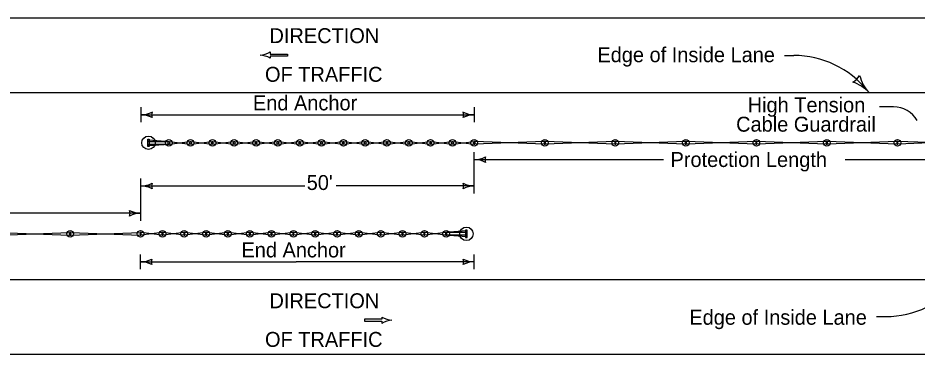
# Model space of a CAD drawing. Extents: x 10133 to 81668, y 7924 to 11018.
# Drawn here: x 10688 to 11411, y 8927 to 9197 of the extents above; entities that cross this region are included whole.
import ezdxf

# ---------------------------------------------------------------- set-up
doc = ezdxf.new("R2010")
doc.units = 0
for name, color, linetype in [('dsnCellElements', 7, 'Continuous'), ('DsnShtRevisedText', 7, 'Continuous'), ('dsnStdDimension', 7, 'Continuous')]:
    doc.layers.add(name, color=color, linetype=linetype)

msp = doc.modelspace()

# ---------------------------------------------------------------- linework, layer by layer
at = {"layer": 'dsnCellElements'}
for p, q in [((10793.26, 9099.32), (10810.02, 9098.13)), ((10793.26, 9098.13), (10809.09, 9098.13)), ((10793.26, 9095.88), (10809.09, 9095.88)), ((10793.26, 9094.7), (10810.02, 9095.88)), ((10810.02, 9095.88), (10826.6, 9098.14)), ((10810.02, 9098.13), (10826.6, 9095.89)), ((10827.54, 9098.14), (10844.17, 9095.88)), ((10827.54, 9095.89), (10844.17, 9098.13)), ((10845.12, 9095.88), (10861.7, 9098.14)), ((10845.12, 9098.13), (10861.7, 9095.89)), ((10862.64, 9098.14), (10879.27, 9095.88)), ((10862.64, 9095.89), (10879.27, 9098.13)), ((10880.22, 9095.88), (10896.8, 9098.14)), ((10880.22, 9098.13), (10896.8, 9095.89)), ((10897.74, 9098.14), (10914.37, 9095.88)), ((10897.74, 9095.89), (10914.37, 9098.13)), ((10915.31, 9095.88), (10931.89, 9098.14)), ((10915.31, 9098.13), (10931.89, 9095.89)), ((10932.83, 9098.14), (10949.46, 9095.88)), ((10932.83, 9095.89), (10949.46, 9098.14)), ((10950.4, 9098.14), (10966.98, 9095.89)), ((10950.4, 9095.88), (10966.98, 9098.14)), ((10967.92, 9098.14), (10984.55, 9095.89)), ((10967.92, 9095.89), (10984.55, 9098.14)), ((10985.49, 9098.14), (11002.07, 9095.89)), ((10985.49, 9095.89), (11002.07, 9098.14)), ((11003.01, 9098.14), (11019.64, 9095.89)), ((11003.01, 9095.89), (11019.64, 9098.14)), ((11020.58, 9098.14), (11037.16, 9095.89)), ((11020.58, 9095.89), (11037.16, 9098.14)), ((11038.1, 9098.14), (11054.73, 9095.89)), ((11038.1, 9095.89), (11054.73, 9098.14)), ((11111.43, 9098.14), (11055.67, 9095.89)), ((11111.43, 9095.89), (11055.67, 9098.14)), ((11168.14, 9098.14), (11112.37, 9095.89)), ((11168.14, 9095.89), (11112.37, 9098.14)), ((11224.84, 9098.14), (11169.08, 9095.89)), ((11224.84, 9095.89), (11169.08, 9098.14)), ((11281.54, 9098.14), (11225.78, 9095.89)), ((11281.54, 9095.89), (11225.78, 9098.14)), ((11338.24, 9098.14), (11282.48, 9095.89)), ((11338.24, 9095.89), (11282.48, 9098.14)), ((11394.94, 9098.14), (11339.18, 9095.89)), ((11394.94, 9095.89), (11339.18, 9098.14)), ((11451.64, 9098.14), (11395.88, 9095.89)), ((11451.64, 9095.89), (11395.88, 9098.14)), ((10674, 9022.69), (10729.76, 9024.94)), ((10674, 9024.94), (10729.76, 9022.69)), ((10730.7, 9022.69), (10786.46, 9024.94)), ((10730.7, 9024.94), (10786.46, 9022.69)), ((10804.03, 9024.94), (10787.4, 9022.69)), ((10804.03, 9022.69), (10787.4, 9024.94)), ((10821.55, 9024.94), (10804.97, 9022.69)), ((10821.55, 9022.69), (10804.97, 9024.94)), ((10839.12, 9024.94), (10822.49, 9022.69)), ((10839.12, 9022.69), (10822.49, 9024.94)), ((10856.64, 9024.94), (10840.06, 9022.69)), ((10856.64, 9022.69), (10840.06, 9024.94)), ((10874.21, 9024.94), (10857.58, 9022.69)), ((10874.21, 9022.69), (10857.58, 9024.94)), ((10891.73, 9024.94), (10875.15, 9022.69)), ((10891.73, 9022.69), (10875.15, 9024.94)), ((10909.3, 9024.94), (10892.67, 9022.69)), ((10909.3, 9022.69), (10892.67, 9024.94)), ((10926.82, 9022.69), (10910.24, 9024.94)), ((10926.82, 9024.94), (10910.24, 9022.69)), ((10944.39, 9024.94), (10927.76, 9022.69)), ((10944.39, 9022.69), (10927.76, 9024.94)), ((10961.91, 9024.94), (10945.33, 9022.69)), ((10961.91, 9022.69), (10945.33, 9024.94)), ((10979.49, 9024.94), (10962.86, 9022.69)), ((10979.49, 9022.69), (10962.86, 9024.94)), ((10997.02, 9024.94), (10980.43, 9022.69)), ((10997.02, 9022.69), (10980.43, 9024.94)), ((11014.6, 9024.94), (10997.96, 9022.69)), ((11014.6, 9022.69), (10997.96, 9024.94)), ((11032.12, 9024.94), (11015.53, 9022.69)), ((11032.12, 9022.69), (11015.53, 9024.94)), ((11048.88, 9026.12), (11032.12, 9024.94)), ((11048.88, 9021.51), (11032.12, 9022.69)), ((11048.88, 9024.94), (11033.05, 9024.94)), ((11048.88, 9022.69), (11033.05, 9022.69))]:
    msp.add_line(p, q, dxfattribs=at)
for points in [[(10792.65, 9094.01), (10792.65, 9100.02), (10793.87, 9100.02), (10793.87, 9094.01)], [(10809.08, 9095.88), (10809.08, 9098.13), (10810.02, 9098.13), (10810.02, 9095.88)], [(10826.6, 9095.89), (10826.6, 9098.14), (10827.54, 9098.14), (10827.54, 9095.89)], [(10844.18, 9095.88), (10844.18, 9098.13), (10845.12, 9098.13), (10845.12, 9095.88)], [(10861.7, 9095.89), (10861.7, 9098.14), (10862.64, 9098.14), (10862.64, 9095.89)], [(10879.28, 9095.88), (10879.28, 9098.13), (10880.22, 9098.13), (10880.22, 9095.88)], [(10896.8, 9095.89), (10896.8, 9098.14), (10897.74, 9098.14), (10897.74, 9095.89)], [(10914.37, 9095.88), (10914.37, 9098.13), (10915.31, 9098.13), (10915.31, 9095.88)], [(10931.89, 9095.89), (10931.89, 9098.14), (10932.83, 9098.14), (10932.83, 9095.89)], [(10949.46, 9095.88), (10949.46, 9098.14), (10950.4, 9098.14), (10950.4, 9095.88)], [(10966.98, 9095.89), (10966.98, 9098.14), (10967.92, 9098.14), (10967.92, 9095.89)], [(10984.55, 9095.89), (10984.55, 9098.14), (10985.49, 9098.14), (10985.49, 9095.89)], [(11002.07, 9095.89), (11002.07, 9098.14), (11003.01, 9098.14), (11003.01, 9095.89)], [(11019.64, 9095.89), (11019.64, 9098.14), (11020.58, 9098.14), (11020.58, 9095.89)], [(11037.16, 9095.89), (11037.16, 9098.14), (11038.1, 9098.14), (11038.1, 9095.89)], [(11055.67, 9095.89), (11055.67, 9098.14), (11054.73, 9098.14), (11054.73, 9095.89)], [(11054.73, 9095.89), (11054.73, 9098.14), (11055.67, 9098.14), (11055.67, 9095.89)], [(11112.37, 9095.89), (11112.37, 9098.14), (11111.43, 9098.14), (11111.43, 9095.89)], [(11112.37, 9095.89), (11112.37, 9098.14), (11111.43, 9098.14), (11111.43, 9095.89)], [(11169.08, 9095.89), (11169.08, 9098.14), (11168.14, 9098.14), (11168.14, 9095.89)], [(11169.08, 9095.89), (11169.08, 9098.14), (11168.14, 9098.14), (11168.14, 9095.89)], [(11225.78, 9095.89), (11225.78, 9098.14), (11224.84, 9098.14), (11224.84, 9095.89)], [(11225.78, 9095.89), (11225.78, 9098.14), (11224.84, 9098.14), (11224.84, 9095.89)], [(11282.48, 9095.89), (11282.48, 9098.14), (11281.54, 9098.14), (11281.54, 9095.89)], [(11282.48, 9095.89), (11282.48, 9098.14), (11281.54, 9098.14), (11281.54, 9095.89)], [(11339.18, 9095.89), (11339.18, 9098.14), (11338.24, 9098.14), (11338.24, 9095.89)], [(11339.18, 9095.89), (11339.18, 9098.14), (11338.24, 9098.14), (11338.24, 9095.89)], [(11395.88, 9095.89), (11395.88, 9098.14), (11394.94, 9098.14), (11394.94, 9095.89)], [(11395.88, 9095.89), (11395.88, 9098.14), (11394.94, 9098.14), (11394.94, 9095.89)], [(10729.76, 9024.94), (10729.76, 9022.69), (10730.7, 9022.69), (10730.7, 9024.94)], [(10729.76, 9024.94), (10729.76, 9022.69), (10730.7, 9022.69), (10730.7, 9024.94)], [(10786.46, 9024.94), (10786.46, 9022.69), (10787.4, 9022.69), (10787.4, 9024.94)], [(10787.4, 9022.69), (10787.4, 9024.94), (10786.46, 9024.94), (10786.46, 9022.69)], [(10804.97, 9022.69), (10804.97, 9024.94), (10804.03, 9024.94), (10804.03, 9022.69)], [(10822.49, 9022.69), (10822.49, 9024.94), (10821.55, 9024.94), (10821.55, 9022.69)], [(10840.06, 9022.69), (10840.06, 9024.94), (10839.12, 9024.94), (10839.12, 9022.69)], [(10857.58, 9022.69), (10857.58, 9024.94), (10856.64, 9024.94), (10856.64, 9022.69)], [(10875.15, 9022.69), (10875.15, 9024.94), (10874.21, 9024.94), (10874.21, 9022.69)], [(10892.67, 9022.69), (10892.67, 9024.94), (10891.73, 9024.94), (10891.73, 9022.69)], [(10910.24, 9022.69), (10910.24, 9024.94), (10909.3, 9024.94), (10909.3, 9022.69)], [(10927.76, 9022.69), (10927.76, 9024.94), (10926.82, 9024.94), (10926.82, 9022.69)], [(10945.33, 9022.69), (10945.33, 9024.94), (10944.39, 9024.94), (10944.39, 9022.69)], [(10962.85, 9022.69), (10962.85, 9024.94), (10961.91, 9024.94), (10961.91, 9022.69)], [(10980.43, 9022.69), (10980.43, 9024.94), (10979.49, 9024.94), (10979.49, 9022.69)], [(10997.95, 9022.69), (10997.95, 9024.94), (10997.02, 9024.94), (10997.02, 9022.69)], [(11015.53, 9022.69), (11015.53, 9024.94), (11014.6, 9024.94), (11014.6, 9022.69)], [(11033.05, 9022.69), (11033.05, 9024.94), (11032.12, 9024.94), (11032.12, 9022.69)], [(11049.48, 9020.81), (11049.48, 9026.82), (11048.27, 9026.82), (11048.27, 9020.81)]]:
    msp.add_lwpolyline(points, close=True, dxfattribs=at)
for centre, radius in [((10793.26, 9097.01), 5.4), ((10809.55, 9097.01), 2.66), ((10827.07, 9097.01), 2.66), ((10844.65, 9097.01), 2.66), ((10862.17, 9097.01), 2.66), ((10879.75, 9097.01), 2.66), ((10897.27, 9097.01), 2.66), ((10914.84, 9097.01), 2.66), ((10932.36, 9097.01), 2.66), ((10949.93, 9097.01), 2.66), ((10967.45, 9097.01), 2.66), ((10985.02, 9097.01), 2.66), ((11002.54, 9097.01), 2.66), ((11020.11, 9097.01), 2.66), ((11037.63, 9097.01), 2.66), ((11055.2, 9097.01), 2.66), ((11055.2, 9097.01), 2.66), ((11111.9, 9097.01), 2.66), ((11111.9, 9097.01), 2.66), ((11168.61, 9097.01), 2.66), ((11168.61, 9097.01), 2.66), ((11225.31, 9097.01), 2.66), ((11225.31, 9097.01), 2.66), ((11282.01, 9097.01), 2.66), ((11282.01, 9097.01), 2.66), ((11338.71, 9097.01), 2.66), ((11338.71, 9097.01), 2.66), ((11395.41, 9097.01), 2.66), ((11395.41, 9097.01), 2.66), ((11048.88, 9023.82), 5.4), ((10730.23, 9023.82), 2.66), ((10730.23, 9023.82), 2.66), ((10786.93, 9023.82), 2.66), ((10786.93, 9023.82), 2.66), ((10804.5, 9023.82), 2.66), ((10822.02, 9023.82), 2.66), ((10839.59, 9023.82), 2.66), ((10857.11, 9023.82), 2.66), ((10874.68, 9023.82), 2.66), ((10892.2, 9023.82), 2.66), ((10909.77, 9023.82), 2.66), ((10927.29, 9023.82), 2.66), ((10944.86, 9023.82), 2.66), ((10962.38, 9023.82), 2.66), ((10979.96, 9023.82), 2.66), ((10997.48, 9023.82), 2.66), ((11015.06, 9023.82), 2.66), ((11032.59, 9023.82), 2.66)]:
    msp.add_circle(centre, radius, dxfattribs=at)
at = {"layer": 'DsnShtRevisedText'}
for p, q in [((10882.95, 9167.45), (10882.95, 9167.45)), ((10891.05, 9169.99), (10891.05, 9168.21)), ((10891.05, 9168.21), (10905.02, 9168.21)), ((10905.02, 9166.69), (10891.05, 9166.69)), ((10891.05, 9166.69), (10891.05, 9164.91)), ((10905.02, 9168.21), (10905.02, 9166.69)), ((11304.72, 9167.13), (11312.16, 9167.13)), ((10787.1, 9125.49), (10787.1, 9113.49)), ((11055.2, 9125.49), (11055.2, 9113.49)), ((11392.4, 9125.82), (11381.15, 9125.82)), ((10787.1, 9119.49), (11055.2, 9119.49)), ((11055.2, 9056.27), (11055.2, 9089.49)), ((11055.2, 9083.49), (11207.39, 9083.49)), ((11353.36, 9083.49), (11471.89, 9083.49)), ((10787.1, 9034.37), (10787.1, 9068.27)), ((10787.1, 9062.27), (10919.01, 9062.27)), ((11055.2, 9062.27), (10944.03, 9062.27)), ((10787.1, 9040.37), (10572.76, 9040.37)), ((10786.93, 8995.34), (10786.93, 9007.34)), ((11055.2, 8995.34), (11055.2, 9007.34)), ((10786.93, 9001.34), (10911.91, 9001.34)), ((11055.2, 9001.34), (10911.91, 9001.34)), ((10980.89, 8956.98), (10980.89, 8955.2)), ((11378.63, 8957.41), (11386.08, 8957.41)), ((10980.89, 8955.2), (10966.93, 8955.2)), ((10966.93, 8955.2), (10966.93, 8953.68)), ((10966.93, 8953.68), (10980.89, 8953.68)), ((10980.89, 8953.68), (10980.89, 8951.9)), ((10988.99, 8954.44), (10988.99, 8954.44))]:
    msp.add_line(p, q, dxfattribs=at)
for centre, radius, start, end in [((10882.28, 9183.81), 16.37, 272.35199, 302.38203), ((10882.28, 9151.09), 16.37, 57.61797, 87.64801), ((11312.16, 9090.94), 76.18, 39.01063, 90), ((11354.17, 9157.13), 12.51, 295.26394, 330.73064), ((11349, 9115.19), 32.38, 42.99729, 71.06977), ((11396.36, 9159.35), 32.38, 194.9248, 222.99729), ((11392.4, 9104.06), 21.76, 30.22434, 90), ((10787.1, 9138.61), 19.13, 270, 298.07249), ((10787.1, 9100.36), 19.13, 61.92751, 90), ((10803.13, 9119.49), 7.39, 162.26665, 197.73335), ((11039.17, 9119.49), 7.39, 342.26665, 17.73335), ((11055.2, 9138.61), 19.13, 241.92751, 270), ((11055.2, 9100.36), 19.13, 90, 118.07249), ((11055.2, 9102.61), 19.13, 270, 298.07249), ((11055.2, 9064.36), 19.13, 61.92751, 90), ((11071.24, 9083.49), 7.39, 162.26665, 197.73335), ((10787.1, 9081.39), 19.13, 270, 298.07249), ((10787.1, 9043.14), 19.13, 61.92751, 90), ((10803.13, 9062.27), 7.39, 162.26665, 197.73335), ((11039.17, 9062.27), 7.39, 342.26665, 17.73335), ((11055.2, 9081.39), 19.13, 241.92751, 270), ((11055.2, 9043.14), 19.13, 90, 118.07249), ((10771.06, 9040.37), 7.39, 342.26665, 17.73335), ((10787.1, 9059.5), 19.13, 241.92751, 270), ((10787.1, 9021.25), 19.13, 90, 118.07249), ((10786.93, 9020.47), 19.13, 270, 298.07249), ((10786.93, 8982.22), 19.13, 61.92751, 90), ((10802.97, 9001.34), 7.39, 162.26665, 197.73335), ((11039.17, 9001.34), 7.39, 342.26665, 17.73335), ((11055.2, 9020.47), 19.13, 241.92751, 270), ((11055.2, 8982.22), 19.13, 90, 118.07249), ((11386.08, 9033.59), 76.18, 270, 320.98937), ((10989.66, 8970.8), 16.37, 237.61797, 267.64801), ((10989.66, 8938.08), 16.37, 92.35199, 122.38203)]:
    msp.add_arc(centre, radius, start, end, dxfattribs=at)
at = {"layer": 'dsnStdDimension'}
for p, q in [((10362.19, 9197.27), (11477.85, 9197.27)), ((10362.19, 9137.27), (11477.85, 9137.27)), ((10362.19, 8987.27), (11477.85, 8987.27)), ((10362.19, 8927.27), (11477.85, 8927.27))]:
    msp.add_line(p, q, dxfattribs=at)

# ---------------------------------------------------------------- texts
at = {"layer": 'DsnShtRevisedText'}
for s, p in [('DIRECTION', (10890.54, 9177.07)), ('Edge of Inside Lane', (11154.21, 9161.77)), ('OF TRAFFIC', (10886.94, 9146.01)), ('End Anchor', (10877.24, 9123.05)), ('High Tension', (11275.05, 9121.46)), ('Cable Guardrail', (11265.76, 9105.93)), ('Protection Length', (11213, 9077.54)), ("50'", (10920.44, 9059.07)), ('End Anchor', (10868, 9004.9)), ('DIRECTION', (10890.54, 8964.06)), ('Edge of Inside Lane', (11228.13, 8950.77)), ('OF TRAFFIC', (10886.94, 8933))]:
    msp.add_text(s, height=12, dxfattribs=at).set_placement(p)

doc.saveas('drawing.dxf')
